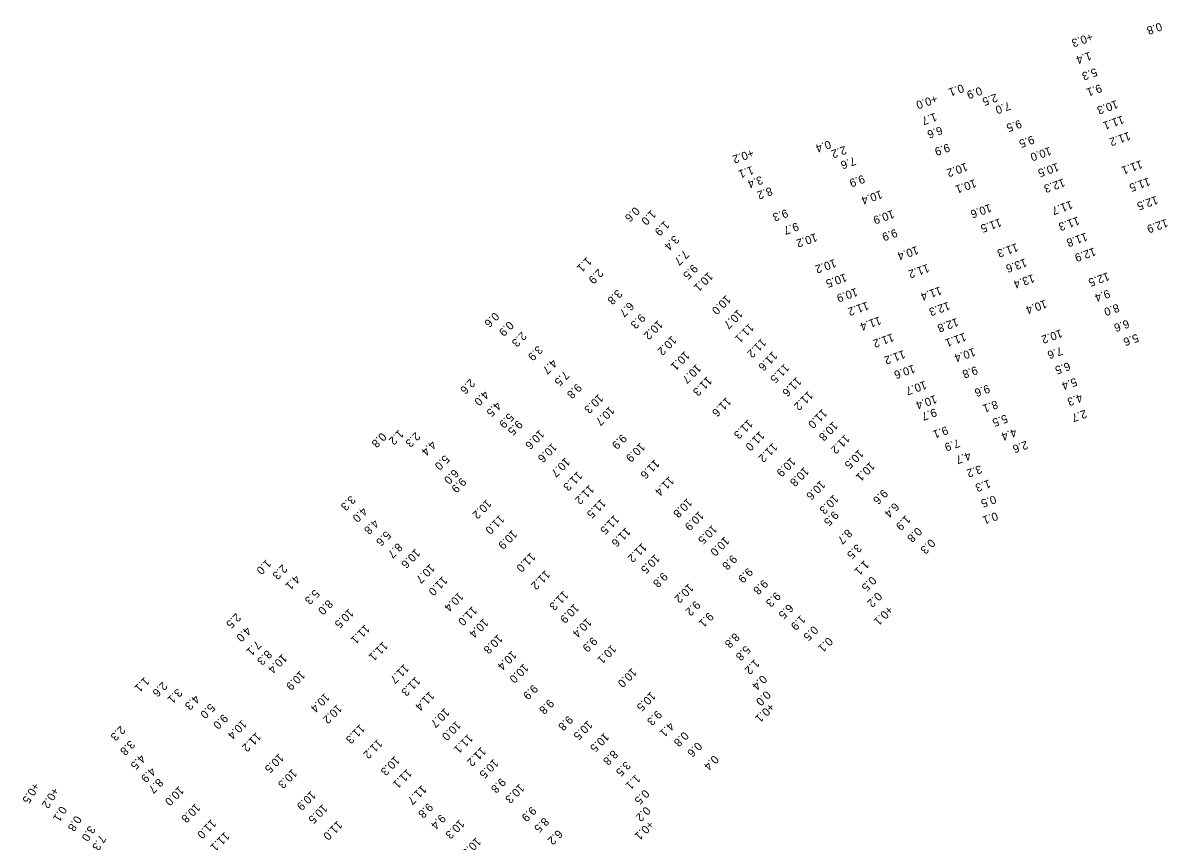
# Model space of a CAD drawing. Extents: x 815385 to 820851, y 582449 to 604245.
# Drawn here: x 816563 to 817257, y 599350 to 599849 of the extents above; entities that cross this region are included whole.
import ezdxf

# ---------------------------------------------------------------- set-up
doc = ezdxf.new("R2010")
doc.units = 0
doc.layers.add('V-TOPO-SOUN-021909', color=7, linetype='Continuous')

msp = doc.modelspace()

# ---------------------------------------------------------------- texts
at = {"layer": 'V-TOPO-SOUN-021909'}
for s, rotation, p in [('0.8', 199.431, (817256.26, 599849.12)), ('+0.3 ', 199.431, (817214.12, 599842.83)), ('1.4', 199.431, (817213.21, 599831.26)), ('5.3', 199.431, (817216.74, 599821.37)), ('0.1', 199.431, (817135.41, 599811.57)), ('0.9', 199.431, (817146.51, 599809.94)), ('9.1', 199.431, (817219.53, 599811.54)), ('+0.0 ', 199.431, (817119.28, 599805.07)), ('2.5', 199.431, (817155.96, 599805.8)), ('10.3 ', 199.431, (817229.43, 599801.78)), ('7.0', 199.431, (817163.94, 599800.77)), ('1.7', 199.431, (817118.97, 599794.08)), ('9.5', 199.431, (817170.66, 599789.85)), ('11.1 ', 199.431, (817233.1, 599792.38)), ('6.6', 199.431, (817122.39, 599785.86)), ('11.2 ', 199.431, (817237, 599782.45)), ('0.4', 199.431, (817054.36, 599777.31)), ('2.2', 199.431, (817063.83, 599773.86)), ('9.9', 199.431, (817126.92, 599775.32)), ('9.5', 199.431, (817178.37, 599780.19)), ('+0.2 ', 199.431, (817007.35, 599771.97)), ('7.6', 199.431, (817069.59, 599767.17)), ('10.0 ', 199.431, (817188.79, 599773.26)), ('1.1', 199.431, (817007.26, 599761.59)), ('10.2 ', 199.431, (817137.75, 599763.59)), ('10.5 ', 199.431, (817193.4, 599763.54)), ('11.1 ', 199.431, (817244.4, 599765.13)), ('3.4', 199.431, (817012.83, 599755.58)), ('9.9', 199.431, (817074.97, 599756.21)), ('10.1 ', 199.431, (817143.02, 599753.57)), ('12.3 ', 199.431, (817197.08, 599753.95)), ('11.5 ', 199.431, (817249.05, 599754.6)), ('8.2', 199.431, (817018.65, 599748.76)), ('10.4 ', 199.431, (817085.71, 599746.77)), ('11.7 ', 199.431, (817201.81, 599740.51)), ('12.5 ', 199.431, (817253.78, 599743.37)), ('0.6', 225.026, (816935.84, 599736.99)), ('1.0', 225.026, (816945.85, 599735)), ('9.3', 199.431, (817028.18, 599735.35)), ('10.9 ', 199.431, (817092.97, 599734.82)), ('10.6 ', 199.431, (817152.27, 599738.49)), ('1.9', 225.026, (816953.99, 599728.48)), ('9.7', 199.431, (817034.72, 599727.21)), ('11.5 ', 199.431, (817158.43, 599729.68)), ('11.3 ', 199.431, (817205.96, 599730.75)), ('12.9 ', 199.431, (817259.85, 599729.39)), ('3.4', 225.026, (816959.9, 599719.61)), ('10.2 ', 199.431, (817046.02, 599720.65)), ('9.9', 199.431, (817094.86, 599723.33)), ('11.8 ', 199.431, (817210.81, 599720.97)), ('10.4 ', 199.431, (817107.72, 599712.82)), ('11.3 ', 199.431, (817168.53, 599714.49)), ('12.9 ', 199.431, (817215.87, 599711.9)), ('1.1', 225.026, (816906.58, 599706.25)), ('7.7', 225.026, (816965.88, 599710.49)), ('10.2 ', 199.431, (817057.58, 599704.88)), ('13.6 ', 199.431, (817173.83, 599705.23)), ('2.9', 225.026, (816913.66, 599699.18)), ('9.5', 225.026, (816971.26, 599701.91)), ('11.2 ', 199.431, (817114.33, 599701.88)), ('10.1 ', 225.026, (816980.59, 599697.08)), ('10.5 ', 199.431, (817064.03, 599696.12)), ('13.4 ', 199.431, (817178.54, 599695.65)), ('12.5 ', 199.431, (817224.19, 599696.79)), ('3.8', 225.026, (816925.18, 599686.55)), ('10.9 ', 199.431, (817070.67, 599687.26)), ('11.4 ', 199.431, (817121.9, 599688.15)), ('9.4', 199.431, (817224.54, 599686.25)), ('6.7', 225.026, (816932.37, 599679)), ('10.0 ', 225.026, (816991.48, 599683.09)), ('11.2 ', 199.431, (817077.42, 599678.94)), ('12.3 ', 199.431, (817126.96, 599678.84)), ('10.4 ', 199.431, (817186.04, 599680.04)), ('8.0', 199.431, (817230.18, 599677.62)), ('0.6', 225.026, (816850.16, 599672.69)), ('9.3', 225.026, (816939.33, 599671.8)), ('10.7 ', 225.026, (816998.71, 599674.35)), ('11.4 ', 199.431, (817084.99, 599669.86)), ('0.9', 225.026, (816859, 599667.25)), ('10.2 ', 225.026, (816949.96, 599667.79)), ('11.1 ', 225.026, (817005.51, 599665.88)), ('12.8 ', 199.431, (817132.1, 599668.91)), ('6.6', 199.431, (817236.26, 599667.95)), ('2.3', 225.026, (816866.87, 599660.77)), ('10.2 ', 225.026, (816958.35, 599658.28)), ('11.2 ', 225.026, (817013.04, 599656.73)), ('11.2 ', 199.431, (817092.81, 599659.55)), ('11.1 ', 199.431, (817136.85, 599659.92)), ('10.2 ', 199.431, (817195.51, 599662.02)), ('5.6', 199.431, (817241.98, 599659.33)), ('3.9', 225.026, (816876.71, 599652.33)), ('10.1 ', 225.026, (816966.4, 599648.98)), ('11.6 ', 225.026, (817019.9, 599648.77)), ('11.2 ', 199.431, (817099.68, 599649.33)), ('10.4 ', 199.431, (817142.48, 599650.71)), ('7.6', 199.431, (817195.68, 599651.38)), ('4.7', 225.026, (816885.54, 599644.12)), ('6.5', 199.431, (817200.32, 599642.06)), ('7.5', 225.026, (816892.89, 599636.85)), ('10.7 ', 225.026, (816973.38, 599641.05)), ('11.5 ', 225.026, (817027.08, 599641.29)), ('10.6 ', 199.431, (817105.66, 599640.5)), ('9.8', 199.431, (817143.82, 599639.62)), ('2.6', 225.026, (816835.44, 599632.02)), ('9.8', 225.026, (816900.53, 599629.22)), ('11.3 ', 225.026, (816979.97, 599633.44)), ('11.6 ', 225.026, (817034.51, 599633.1)), ('10.7 ', 199.431, (817112.72, 599630.61)), ('9.6', 199.431, (817151.25, 599628.32)), ('5.4', 199.431, (817204.43, 599632.48)), ('4.0', 225.026, (816843.98, 599624.91)), ('10.3 ', 225.026, (816913.71, 599622.81)), ('11.6 ', 225.026, (816991.61, 599620.82)), ('11.2 ', 225.026, (817041.57, 599624.61)), ('10.4 ', 199.431, (817118.95, 599621.95)), ('4.3', 199.431, (817207.77, 599622.8)), ('4.5', 225.026, (816851.47, 599618.17)), ('10.7 ', 225.026, (816920.5, 599615.39)), ('9.7', 199.431, (817118.87, 599613.86)), ('8.1', 199.431, (817156.19, 599618.7)), ('5.9', 225.026, (816859.07, 599611.22)), ('11.3 ', 225.026, (817004.88, 599607.27)), ('11.0 ', 225.026, (817050.2, 599613.66)), ('5.5', 199.431, (817162.12, 599610.09)), ('2.7', 199.431, (817210.4, 599613.03)), ('1.2', 225.026, (816791.89, 599600.99)), ('9.5', 225.026, (816864.42, 599606.83)), ('10.6 ', 225.026, (816877.71, 599600.95)), ('11.0 ', 225.026, (817011.99, 599600.01)), ('10.8 ', 225.026, (817056.75, 599606.04)), ('9.1', 199.431, (817125.82, 599602.94)), ('4.4', 199.431, (817167.61, 599601.59)), ('0.8', 225.026, (816781.39, 599599.34)), ('2.3', 225.026, (816802.02, 599599.6)), ('4.4', 225.026, (816811.77, 599594.38)), ('9.9', 225.026, (816927.95, 599598.34)), ('10.9 ', 225.026, (816939.13, 599593.16)), ('11.2 ', 225.026, (817064.02, 599598.14)), ('7.9', 199.431, (817132.95, 599595.14)), ('2.6', 199.431, (817174.48, 599594.04)), ('10.6 ', 225.026, (816885.4, 599592.93)), ('11.2 ', 225.026, (817019.9, 599592.92)), ('10.5 ', 225.026, (817072.45, 599588.96)), ('4.7', 199.431, (817139.73, 599587.39)), ('5.0', 225.026, (816819.9, 599585.63)), ('10.7 ', 225.026, (816893.4, 599584.02)), ('11.6 ', 225.026, (816948, 599582.88)), ('10.9 ', 225.026, (817030.99, 599584.19)), ('10.1 ', 225.026, (817079.31, 599581.39)), ('3.2', 199.431, (817146.44, 599579.22)), ('6.0', 225.026, (816825.55, 599577.03)), ('11.3 ', 225.026, (816900.88, 599575.6)), ('11.4 ', 225.026, (816956.85, 599572.57)), ('10.8 ', 225.026, (817039.1, 599578.27)), ('9.9', 225.026, (816830.05, 599571.82)), ('11.2 ', 225.026, (816908.08, 599567.33)), ('10.6 ', 225.026, (817049.08, 599570.07)), ('1.3', 199.431, (817151.73, 599570.39)), ('3.3', 225.026, (816762.62, 599560.91)), ('10.2 ', 225.026, (816845.51, 599558.5)), ('11.5 ', 225.026, (816915.26, 599558.84)), ('10.8 ', 225.026, (816967.93, 599559.23)), ('10.3 ', 225.026, (817057.09, 599561.42)), ('9.6', 225.026, (817087.18, 599564.76)), ('0.5', 199.431, (817155.13, 599560.86)), ('4.0', 225.026, (816769.78, 599553.83)), ('10.9 ', 225.026, (816974.96, 599551.34)), ('6.4', 225.026, (817094.1, 599556.63)), ('4.8', 225.026, (816776.78, 599546.42)), ('11.0 ', 225.026, (816853.39, 599549.14)), ('11.5 ', 225.026, (816923.42, 599549.06)), ('9.5', 225.026, (817057.17, 599551.54)), ('1.9', 225.026, (817101.06, 599548.88)), ('0.1', 199.431, (817156.15, 599550.61)), ('5.6', 225.026, (816784.1, 599539.34)), ('10.9 ', 225.026, (816861.19, 599539.96)), ('11.6 ', 225.026, (816930.33, 599541.41)), ('10.5 ', 225.026, (816983.08, 599543.02)), ('8.7', 225.026, (817065.4, 599540.47)), ('0.8', 225.026, (817108, 599541.6)), ('8.7', 225.026, (816791.18, 599531.98)), ('11.2 ', 225.026, (816940.19, 599531.96)), ('10.0 ', 225.026, (816990.58, 599535.83)), ('3.5', 225.026, (817071.24, 599531.41)), ('0.3', 225.026, (817116.07, 599534.51)), ('10.6 ', 225.026, (816802.05, 599528.39)), ('11.0 ', 225.026, (816872.35, 599526.06)), ('10.5 ', 225.026, (816948.2, 599525.08)), ('9.8', 225.026, (816995.21, 599524.76)), ('1.0', 225.026, (816711.17, 599521.94)), ('2.3', 225.026, (816720.97, 599518.89)), ('10.7 ', 225.026, (816810.98, 599519.24)), ('9.9', 225.026, (817004.81, 599516.88)), ('1.1', 225.026, (817075.74, 599521.41)), ('4.1', 225.026, (816728.75, 599512.47)), ('11.0 ', 225.026, (816818.73, 599511.69)), ('11.2 ', 225.026, (816881.28, 599515.3)), ('9.8', 225.026, (816952.95, 599514.07)), ('0.5', 225.026, (817080.18, 599511.69)), ('5.3', 225.026, (816740.62, 599503.66)), ('11.3 ', 225.026, (816892.38, 599502.78)), ('10.2 ', 225.026, (816968.73, 599507.17)), ('9.8', 225.026, (817014.11, 599509.69)), ('8.0', 225.026, (816748.74, 599497.41)), ('10.4 ', 225.026, (816828.38, 599501.97)), ('9.2', 225.026, (816972.81, 599496.77)), ('9.3', 225.026, (817021.83, 599502.14)), ('0.2', 225.026, (817083.65, 599501.97)), ('2.5', 225.026, (816692.67, 599489.15)), ('10.5 ', 225.026, (816761.44, 599491.86)), ('11.0 ', 225.026, (816836.76, 599493.39)), ('10.9 ', 225.026, (816898.9, 599494.88)), ('9.1', 225.026, (816980.89, 599489.7)), ('6.5', 225.026, (817029.56, 599494.86)), ('+0.1 ', 225.026, (817090.38, 599493.63)), ('11.1 ', 225.026, (816771.29, 599482.17)), ('10.4 ', 225.026, (816843.61, 599485.96)), ('10.4 ', 225.026, (816906.56, 599486.17)), ('1.9', 225.026, (817037, 599487.98)), ('4.0', 225.026, (816698.93, 599480.94)), ('10.8 ', 225.026, (816852.29, 599476.21)), ('8.8', 225.026, (816996.73, 599477.17)), ('0.5', 225.026, (817044.69, 599481.52)), ('7.1', 225.026, (816705.01, 599472.47)), ('11.1 ', 225.026, (816782.32, 599471.8)), ('9.9', 225.026, (816910, 599474.69)), ('10.1 ', 225.026, (816921.61, 599470)), ('5.8', 225.026, (817003.41, 599469.44)), ('0.1', 225.026, (817053.63, 599474.56)), ('8.3', 225.026, (816711.57, 599466.69)), ('10.4 ', 225.026, (816720.86, 599464.27)), ('10.4 ', 225.026, (816860.85, 599466.2)), ('1.2', 225.026, (817008.95, 599461.02)), ('10.9 ', 225.026, (816731.84, 599454.03)), ('11.7 ', 225.026, (816795.19, 599458.17)), ('10.0 ', 225.026, (816868.1, 599458.41)), ('10.0 ', 225.026, (816934.1, 599455.71)), ('1.1', 225.026, (816636.85, 599450.14)), ('2.6', 225.026, (816647.8, 599447.39)), ('11.3 ', 225.026, (816802.12, 599450.43)), ('0.4', 225.026, (817013.48, 599451.51)), ('3.1', 225.026, (816656.9, 599443.25)), ('10.4 ', 225.026, (816746.81, 599440.5)), ('11.4 ', 225.026, (816810.67, 599441.43)), ('9.9', 225.026, (816873.74, 599445.67)), ('10.5 ', 225.026, (816945.65, 599441.23)), ('0.0', 225.026, (817015.76, 599441.94)), ('4.3', 225.026, (816667.52, 599439.35)), ('5.0', 225.026, (816676.88, 599434.14)), ('10.2 ', 225.026, (816754.27, 599433.57)), ('9.8', 225.026, (816883.56, 599436.77)), ('9.0', 225.026, (816684.77, 599427.65)), ('10.7 ', 225.026, (816819.91, 599431.26)), ('9.8', 225.026, (816895.18, 599426.73)), ('9.3', 225.026, (816949.35, 599429.9)), ('+0.1 ', 225.026, (817018.1, 599434.41)), ('2.3', 225.026, (816622.22, 599420.54)), ('10.4 ', 225.026, (816696.25, 599424.1)), ('11.3 ', 225.026, (816768.31, 599421.41)), ('10.0 ', 225.026, (816826.86, 599423.4)), ('10.5 ', 225.026, (816907.13, 599423.72)), ('4.1', 225.026, (816956.96, 599422.8)), ('11.2 ', 225.026, (816704.97, 599416.51)), ('11.1 ', 225.026, (816834.18, 599415.48)), ('10.5 ', 225.026, (816917.26, 599416.26)), ('0.8', 225.026, (816965.68, 599417.01)), ('3.8', 225.026, (816628.04, 599411.7)), ('11.2 ', 225.026, (816778.97, 599412.29)), ('11.2 ', 225.026, (816842.19, 599407.57)), ('0.6', 225.026, (816973.9, 599410.65)), ('4.5', 225.026, (816634.42, 599403.03)), ('10.5 ', 225.026, (816718.82, 599403.56)), ('10.3 ', 225.026, (816789.56, 599402)), ('10.5 ', 225.026, (816849.74, 599400.27)), ('8.8', 225.026, (816922.53, 599405.68)), ('3.5', 225.026, (816930.33, 599398.93)), ('0.4', 225.026, (816984.01, 599402.59)), ('4.9', 225.026, (816640.74, 599395.19)), ('10.3 ', 225.026, (816726.94, 599394.15)), ('11.1 ', 225.026, (816796.94, 599394.13)), ('+0.5 ', 237.797, (816569.04, 599385.99)), ('8.7', 225.026, (816645.26, 599388.5)), ('9.8', 225.026, (816854.19, 599388.71)), ('10.3 ', 225.026, (816865.54, 599385.12)), ('1.1', 225.026, (816936.33, 599390.79)), ('+0.2 ', 237.797, (816580.91, 599383.06)), ('10.0 ', 225.026, (816657.95, 599383.62)), ('10.9 ', 225.026, (816738.37, 599380.8)), ('11.7 ', 225.026, (816805.92, 599384.3)), ('0.5', 225.026, (816941.74, 599381.7)), ('0.1', 237.797, (816585.68, 599371.62)), ('10.8 ', 225.026, (816667.94, 599373.22)), ('10.5 ', 225.026, (816745.44, 599372.65)), ('9.8', 225.026, (816809.81, 599373.44)), ('9.9', 225.026, (816872.85, 599371.3)), ('0.2', 225.026, (816942.46, 599371.34)), ('0.8', 237.797, (816594.66, 599365.77)), ('9.4', 225.026, (816817.55, 599366.61)), ('8.5', 225.026, (816880.49, 599364.62)), ('3.0', 237.797, (816603.11, 599359.67)), ('11.0 ', 225.026, (816677.67, 599363.51)), ('11.0 ', 225.026, (816754.55, 599362.61)), ('10.3 ', 225.026, (816829.04, 599363.37)), ('6.2', 225.026, (816888.82, 599357.15)), ('+0.1 ', 225.026, (816944.52, 599362.76)), ('7.3', 237.797, (816609.56, 599354.05)), ('11.1 ', 225.026, (816685.72, 599355.75)), ('10.3 ', 225.026, (816839.14, 599352.45))]:
    msp.add_text(s, height=5, rotation=rotation, dxfattribs=at).set_placement(p)

doc.saveas('drawing.dxf')
